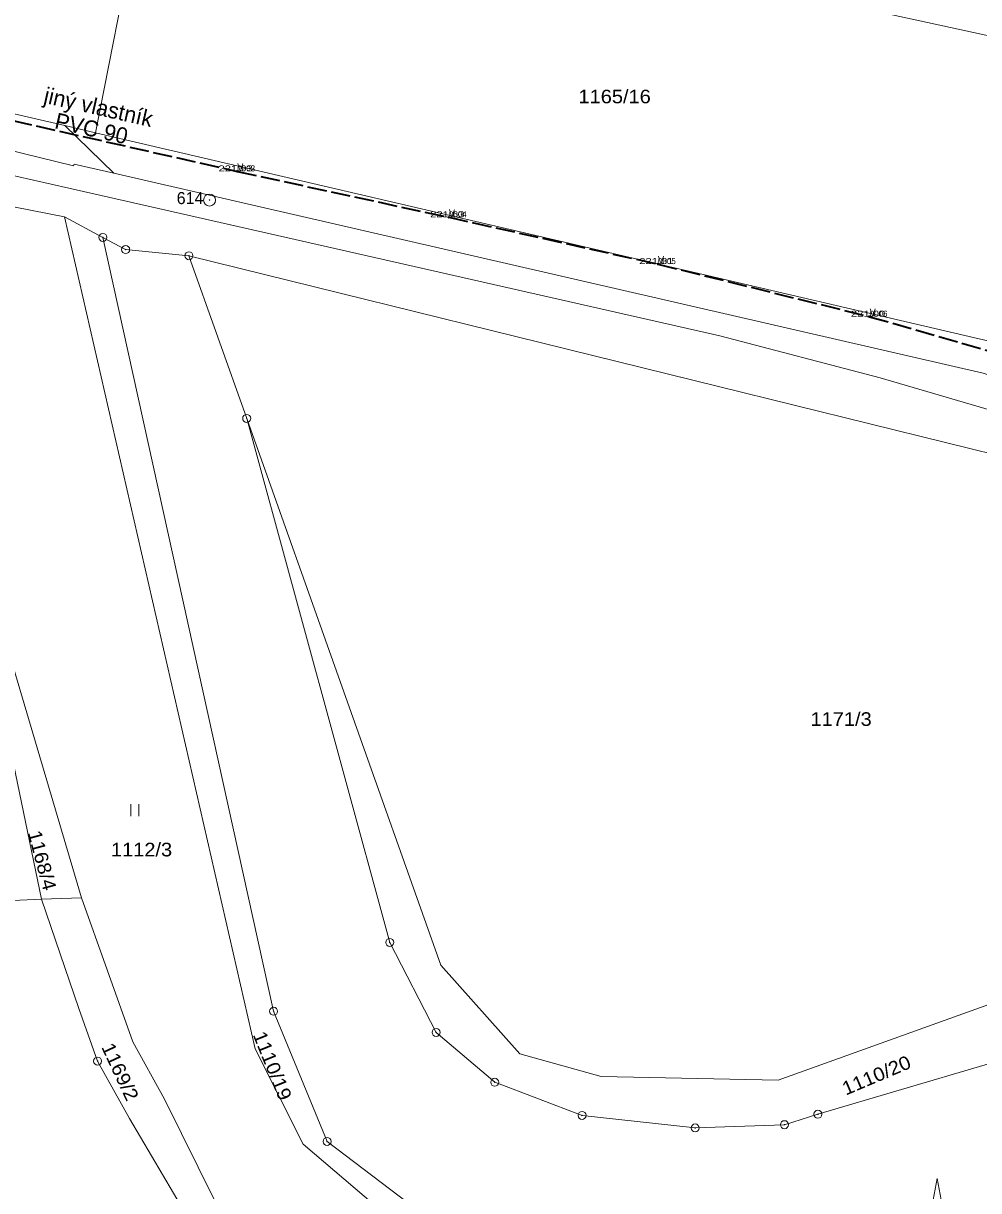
# Model space of a CAD drawing. Extents: x -686207 to -681951, y -1020493 to -1017811.
# Drawn here: x -684214.5 to -684095.1, y -1019323.9 to -1019178.1 of the extents above; entities that cross this region are included whole.
import ezdxf
from ezdxf.enums import TextEntityAlignment as Align

# ---------------------------------------------------------------- set-up
doc = ezdxf.new("R2010")
doc.units = 0
doc.header["$LTSCALE"] = 0.4
doc.header["$PDMODE"] = 32
doc.header["$PDSIZE"] = 0.2
doc.linetypes.add('LONG_DASHED', pattern=[7.5, 6, -1.5])
for name, color, linetype, lineweight in [('1', 7, 'Continuous', 13), ('3', 7, 'Continuous', 13), ('35', 7, 'LONG_DASHED', 35), ('4', 7, 'Continuous', 13), ('6', 7, 'Continuous', 13), ('8', 7, 'Continuous', 13)]:
    doc.layers.add(name, color=color, linetype=linetype, lineweight=lineweight)
doc.layers.add('17', color=7, linetype='Continuous')
doc.layers.add('2', color=7, linetype='Continuous')

msp = doc.modelspace()

# ---------------------------------------------------------------- linework, layer by layer
at = {"layer": '1'}
for p, q in [((-684084.87, -1019181.63), (-684199.82, -1019156.49)), ((-684262.82, -1019178.4), (-684209.29, -1019190.88)), ((-684209.29, -1019190.88), (-684203.15, -1019196.83)), ((-684205.44, -1019191.78), (-684209.29, -1019190.88)), ((-684219.03, -1019200.36), (-684209.35, -1019202.26)), ((-684209.35, -1019202.26), (-684204.54, -1019204.84)), ((-684201.69, -1019206.36), (-684204.54, -1019204.84)), ((-684204.54, -1019204.84), (-684183.21, -1019301.53)), ((-684193.78, -1019207.13), (-684201.69, -1019206.36)), ((-684193.78, -1019207.13), (-684186.57, -1019227.46)), ((-684219.43, -1019246.09), (-684207.19, -1019287.34)), ((-684207.19, -1019287.34), (-684212.19, -1019287.54)), ((-684212.19, -1019287.54), (-684230.34, -1019288.29))]:
    msp.add_line(p, q, dxfattribs=at)
for points in [[(-684205.44, -1019191.78), (-684200.51, -1019166.6), (-684200.14, -1019161.17), (-684199.82, -1019156.49)], [(-684203.15, -1019196.83), (-684208.13, -1019195.68), (-684208.2, -1019195.9), (-684263.48, -1019182.35)], [(-684078.71, -1019222.69), (-684092.58, -1019218.1), (-684205.44, -1019191.78)], [(-684203.15, -1019196.83), (-684094.57, -1019221.82), (-684054.3, -1019234.73), (-683955.31, -1019271.3)], [(-684209.35, -1019202.26), (-684185.49, -1019306.24), (-684179.53, -1019318.14), (-684162.86, -1019332.32), (-684154.27, -1019337.22), (-684139, -1019342.47)], [(-683999.7, -1019264.85), (-684070.91, -1019237.48), (-684193.78, -1019207.13)], [(-684186.57, -1019227.46), (-684168.7, -1019292.93), (-684162.9, -1019304.17), (-684155.58, -1019310.4), (-684144.67, -1019314.55), (-684130.54, -1019316.11), (-684119.38, -1019315.7), (-684115.21, -1019314.39), (-684083.87, -1019305.16), (-684044, -1019286.52), (-684024.23, -1019277.45)], [(-684186.57, -1019227.46), (-684162.32, -1019295.76), (-684152.44, -1019306.86), (-684142.29, -1019309.68), (-684120.17, -1019310.13), (-684053.74, -1019286.29), (-684031.45, -1019278.13), (-684025.29, -1019275.77)], [(-684212.19, -1019287.54), (-684217.74, -1019260.95), (-684219.43, -1019246.09)], [(-684184.19, -1019338.1), (-684196.84, -1019312.52), (-684200.81, -1019305.34), (-684207.19, -1019287.34)], [(-684189.99, -1019335.01), (-684190.21, -1019333.6), (-684201.22, -1019314.94), (-684205.19, -1019307.76), (-684207.56, -1019301.2), (-684212.19, -1019287.54)], [(-684183.21, -1019301.53), (-684176.53, -1019317.8), (-684159.56, -1019330.66), (-684131.64, -1019342.43)]]:
    msp.add_lwpolyline(points, dxfattribs=at)
for p in [(-684187.75, -1019196.6), (-684161.31, -1019202.33), (-684135.19, -1019208.18), (-684108.74, -1019214.75)]:
    msp.add_point(p, dxfattribs=at)
at = {"layer": '3'}
for p, q in [((-684201.031, -1019277.17), (-684201.031, -1019275.67)), ((-684200.03, -1019277.17), (-684200.03, -1019275.67))]:
    msp.add_line(p, q, dxfattribs=at)
msp.add_lwpolyline([(-684099.54, -1019326.42), (-684100.29, -1019322.42), (-684101.04, -1019326.42)], dxfattribs=at)
at = {"layer": '35'}
msp.add_lwpolyline([(-684253.32, -1019181.51), (-684218.74, -1019189.57), (-684187.75, -1019196.6), (-684161.31, -1019202.33), (-684135.19, -1019208.18), (-684108.74, -1019214.75), (-684082.37, -1019222.33), (-684055.68, -1019231.47), (-684028.78, -1019241.13), (-684001.7, -1019252), (-683976.78, -1019261.52), (-683963.28, -1019265.94), (-683954.22, -1019264.32), (-683949.59, -1019261.5)], dxfattribs=at)
at = {"layer": '6'}
for p, q in [((-684264.61, -1019186.11), (-684208.8, -1019198.69)), ((-684127.46, -1019217.14), (-684208.8, -1019198.69)), ((-684107.44, -1019222.4), (-684127.46, -1019217.14)), ((-684082.1, -1019229.81), (-684107.44, -1019222.4))]:
    msp.add_line(p, q, dxfattribs=at)
at = {"layer": '8'}
for centre, radius in [((-684191.21, -1019200.1798), 0.75), ((-684191.21, -1019200.1798), 0.03), ((-684204.54, -1019204.8399), 0.5), ((-684204.54, -1019204.8399), 0.0303), ((-684201.69, -1019206.3599), 0.5), ((-684201.69, -1019206.3599), 0.0303), ((-684193.78, -1019207.1299), 0.5), ((-684193.78, -1019207.1299), 0.0303), ((-684186.57, -1019227.4599), 0.5), ((-684186.57, -1019227.4599), 0.0303), ((-684168.7, -1019292.9299), 0.5), ((-684168.7, -1019292.9299), 0.0303), ((-684183.21, -1019301.5299), 0.5), ((-684183.21, -1019301.5299), 0.0303), ((-684162.9, -1019304.1699), 0.5), ((-684162.9, -1019304.1699), 0.0303), ((-684205.19, -1019307.7599), 0.5), ((-684205.19, -1019307.7599), 0.0303), ((-684155.58, -1019310.3999), 0.5), ((-684155.58, -1019310.3999), 0.0303), ((-684144.67, -1019314.5499), 0.5), ((-684144.67, -1019314.5499), 0.0303), ((-684115.21, -1019314.3899), 0.5), ((-684115.21, -1019314.3899), 0.0303), ((-684130.54, -1019316.1099), 0.5), ((-684130.54, -1019316.1099), 0.0303), ((-684119.38, -1019315.6999), 0.5), ((-684119.38, -1019315.6999), 0.0303), ((-684176.53, -1019317.7999), 0.5), ((-684176.53, -1019317.7999), 0.0303)]:
    msp.add_circle(centre, radius, dxfattribs=at)

# ---------------------------------------------------------------- texts
at = {"layer": '17'}
for s, p in [('jiný vlastník', (-684205.3007, -1019189.5419)), ('PVC 90', (-684206.1832, -1019192.2046))]:
    msp.add_text(s, height=2, rotation=347.219, dxfattribs=at).set_placement(p, align=Align.CENTER)
at = {"layer": '2', "width": 1.1}
for s, p in [('1165/16', (-684145.12, -1019188.09)), ('1171/3', (-684116.13, -1019265.87)), ('1112/3', (-684203.53, -1019282.179))]:
    msp.add_text(s, height=1.7, dxfattribs=at).set_placement(p)
at = {"layer": '2'}
for s, p in [('0003', (-684187.75, -1019196.6)), ('0004', (-684161.31, -1019202.33)), ('0005', (-684135.19, -1019208.18)), ('0006', (-684108.74, -1019214.75))]:
    msp.add_text(s, height=0.75, dxfattribs=at).set_placement(p)
at = {"layer": '2', "width": 1.1}
for s, rotation, p in [('1168/4', 285, (-684213.931, -1019279.199)), ('1110/19', 292, (-684185.828, -1019304.458)), ('1169/2', 295, (-684204.77, -1019305.979)), ('1110/20', 23, (-684111.727, -1019312.072))]:
    msp.add_text(s, height=1.7, rotation=rotation, dxfattribs=at).set_placement(p)
at = {"layer": '3', "width": 1.4}
for s, p in [('221 93 ', (-684187.75, -1019196.6)), ('221 63 ', (-684161.31, -1019202.33)), ('221 31 ', (-684135.19, -1019208.18)), ('221 00 ', (-684108.74, -1019214.75))]:
    msp.add_text(s, height=0.75, dxfattribs=at).set_placement(p, align=Align.CENTER)
at = {"layer": '4', "width": 0.85}
for p in [(-684187.75, -1019196.6), (-684161.31, -1019202.33), (-684135.19, -1019208.18), (-684108.74, -1019214.75)]:
    msp.add_text('V', height=1, dxfattribs=at).set_placement(p)
at = {"layer": '8'}
msp.add_text('614', height=1.5, dxfattribs=at).set_placement((-684195.313, -1019200.68))

doc.saveas('drawing.dxf')
